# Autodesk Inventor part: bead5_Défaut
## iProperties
Shininess: 64.0
Length Units: 11269
Angle Units: 11279
Time Units: 11290
Mass Units: 11283
Length Display Precision: 3
Angle Display Precision: 2
Compacted: True
Part Number: bead5_Défaut
Document SubType Name: Modeling
Created: 2006-01
Material: Par défaut
Designer: Fricot
Density: 0.0
Volumn: 0.0
Area: 0.0
PropertySet Name: Model Information
Control State: 0
Master: False
Checked Out: False
Author: Fricot
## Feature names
1. Base1
